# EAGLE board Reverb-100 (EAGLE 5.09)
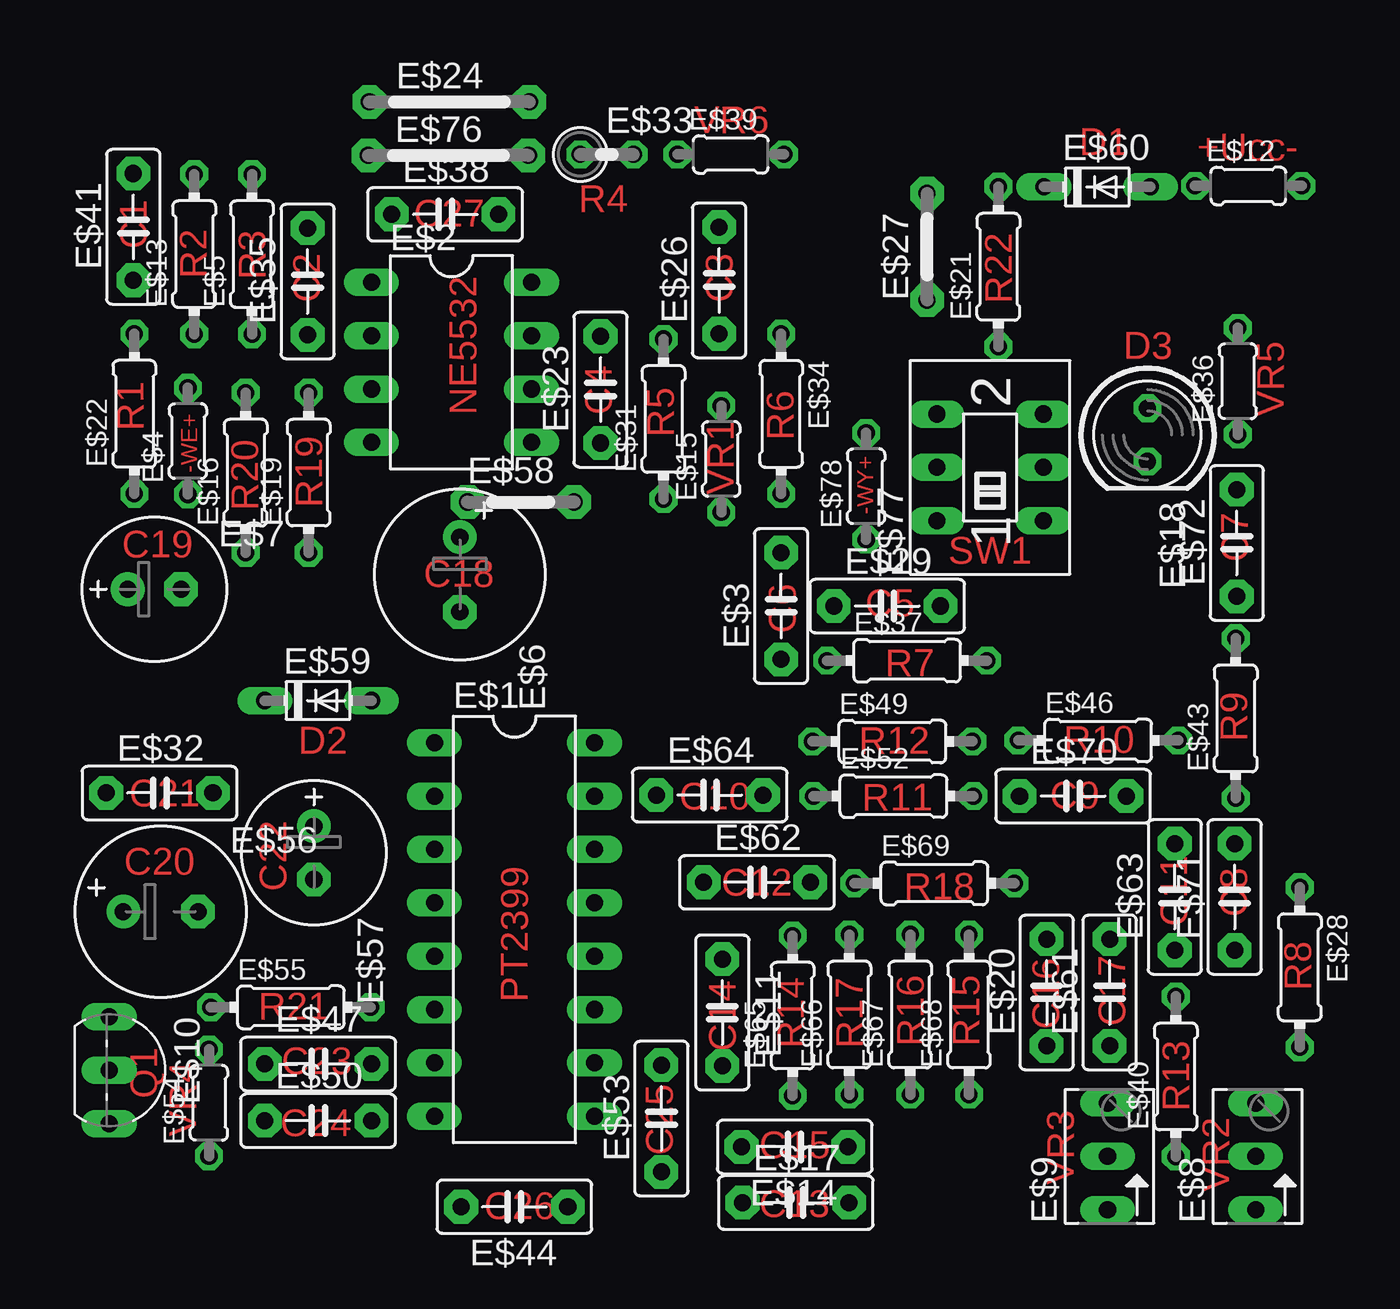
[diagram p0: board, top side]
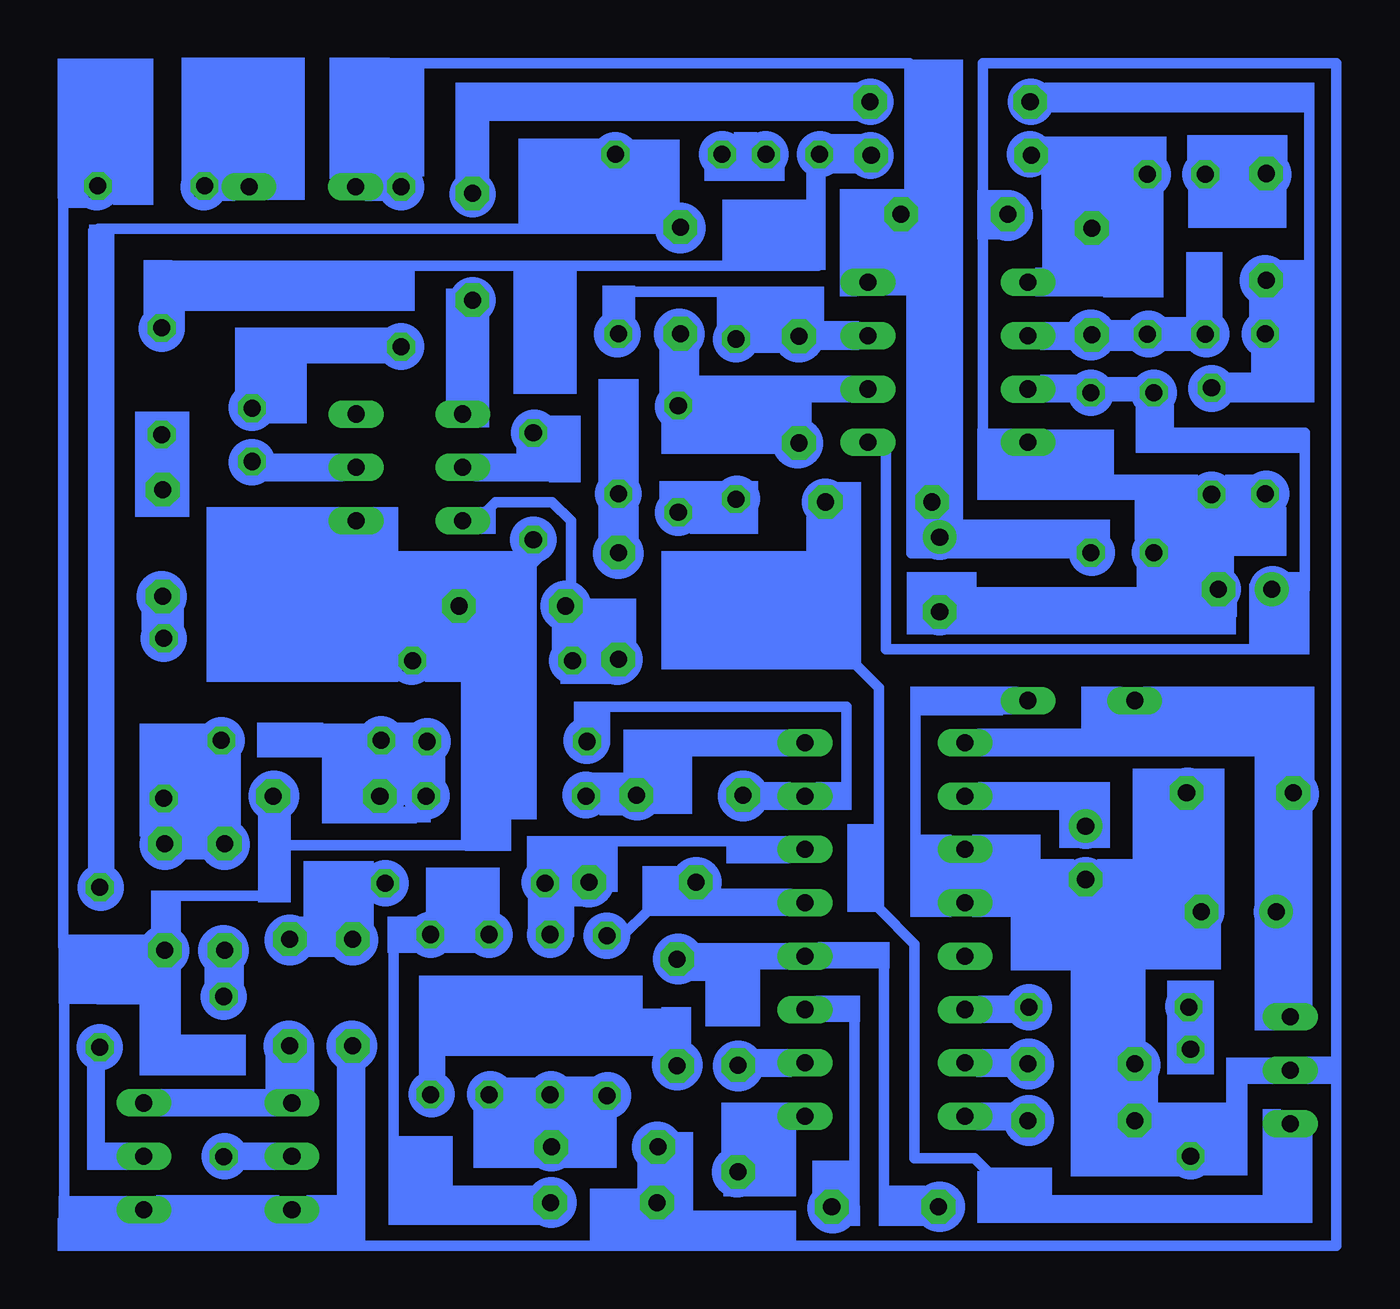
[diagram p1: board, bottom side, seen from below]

No outline drawn. Coordinates in mm, seen from the top.
Copper layers (1*16): Top 0.035mm / dielectric 1.5mm / Bottom 0.035mm
Design rules "default": minimum track width 10mil, minimum drill 24mil, track to track 8mil, track to pad 8mil, pad to pad 8mil, via to via 8mil, smd to smd 8mil, copper to edge 40mil, drill to drill 8mil, minimum pad ring 10mil, minimum via ring 8mil, stop-mask expansion 4mil, vias tented up to drill 0mil, thermal gap 10mil

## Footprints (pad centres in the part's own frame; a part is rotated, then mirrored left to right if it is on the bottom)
DIL16 = drill 0.813 long: 1 -8.89,-3.81; 2 -6.35,-3.81; 3 -3.81,-3.81; 4 -1.27,-3.81; 5 1.27,-3.81; 6 3.81,-3.81; 7 6.35,-3.81; 8 8.89,-3.81; 9 8.89,3.81; 10 6.35,3.81; 11 3.81,3.81; 12 1.27,3.81; 13 -1.27,3.81; 14 -3.81,3.81; 15 -6.35,3.81; 16 -8.89,3.81
DIL08 = drill 0.813 long: 1 -3.81,-3.81; 2 -1.27,-3.81; 3 1.27,-3.81; 4 3.81,-3.81; 5 3.81,3.81; 6 1.27,3.81; 7 -1.27,3.81; 8 -3.81,3.81
C5B2.5 = drill 0.813 pad 1.6 octagon: 1 -2.54,0; 2 2.54,0
0204/5 = drill 0.813 octagon: 1 -2.54,0; 2 2.54,0
0204/7 = drill 0.813 octagon: 1 -3.81,0; 2 3.81,0
E3,5-8 = drill 0.813 pad 1.6 round: + -1.778,0 | drill 0.813 pad 1.6 octagon: - 1.778,0
E2,5-7 = drill 0.813 pad 1.6 round: + -1.27,0 | drill 0.813 pad 1.6 octagon: - 1.27,0
B64Y = drill 0.813 long: A 2.54,0; E -2.54,0; S 0,0
TO92-CBE = drill 0.813 long: B 0,0; C -2.54,0; E 2.54,0
LED5MM = drill 0.813 octagon: A -1.27,0; K 1.27,0
07 = drill 0.813 pad 1.6 octagon: 1 -3.81,0; 2 3.81,0
05 = drill 0.813 pad 1.6 octagon: 1 -2.54,0; 2 2.54,0
0207/2V = drill 0.813 octagon: 1 -1.27,0; 2 1.27,0
DO34-5 = drill 0.813 long: A 2.54,0; C -2.54,0
A68-A31 = drill 0.813 long: 1 -2.54,-2.54; 2 0,-2.54; 3 2.54,-2.54; 4 -2.54,2.54; 5 0,2.54; 6 2.54,2.54

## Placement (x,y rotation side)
E$1  [DIL16]  21.7,15.3 270 top
E$2  [DIL08]  18.7,42.3 270 top
E$3  [C5B2.5]  34.4,30.7 90 top
E$4  [0204/5]  6.15,38.55 90 top
E$5  [0204/7]  9.2,47.45 90 top
E$6  [E3,5-8]  19.1,32.2 270 top
E$7  [E2,5-7]  4.55,31.5 0 top
E$8  [B64Y]  57,4.5 90 top
E$9  [B64Y]  49.95,4.5 90 top
E$10  [TO92-CBE]  2.4,8.6 270 top
E$11  [C5B2.5]  31.6,11.35 270 top
E$12  [0204/5]  56.65,50.7 0 top
E$13  [0204/7]  6.45,47.45 90 top
E$14  [C5B2.5]  35.05,4.95 180 top
E$15  [0204/5]  31.55,37.7 90 top
E$16  [0204/7]  8.9,37.05 90 top
E$17  [C5B2.5]  35.1,2.3 0 top
E$18  [LED5MM]  51.85,38.85 270 top
E$19  [0204/7]  11.9,37.05 90 top
E$20  [C5B2.5]  47.05,12.3 90 top
E$21  [0204/7]  44.75,46.85 90 top
E$22  [0204/7]  3.6,39.85 90 top
E$23  [C5B2.5]  25.8,41 90 top
E$24  [07]  18.6,54.7 0 top
E$26  [C5B2.5]  31.45,46.2 90 top
E$27  [05]  41.35,47.8 90 top
E$28  [0204/7]  59.1,13.5 270 top
E$29  [C5B2.5]  39.45,30.7 0 top
E$31  [0204/7]  28.8,39.6 90 top
E$32  [C5B2.5]  4.8,21.8 0 top
E$33  [0207/2V]  26.1,52.2 0 top
E$34  [0204/7]  34.4,39.85 270 top
E$35  [C5B2.5]  11.85,46.15 90 top
E$36  [0204/5]  56.15,41.4 90 top
E$37  [0204/7]  40.4,28.1 0 top
E$38  [C5B2.5]  18.4,49.35 0 top
E$39  [0204/5]  32,52.2 0 top
E$40  [0204/7]  53.2,8.3 90 top
E$41  [C5B2.5]  3.55,48.75 90 top
E$43  [0204/7]  56.05,25.35 90 top
E$44  [C5B2.5]  21.7,2.1 180 top
E$46  [0204/7]  49.5,24.3 0 top
E$47  [C5B2.5]  12.35,8.9 0 top
E$49  [0204/7]  39.7,24.25 0 top
E$50  [C5B2.5]  12.35,6.2 0 top
E$52  [0204/7]  39.75,21.65 0 top
E$53  [C5B2.5]  28.7,6.3 90 top
E$54  [0204/5]  7.15,7.05 90 top
E$55  [0204/7]  11.05,11.6 0 top
E$56  [E3,5-8]  4.85,16.15 0 top
E$57  [E2,5-7]  12.15,18.95 270 top
E$58  [05]  22,35.65 0 top
E$59  [DO34-5]  12.35,26.2 0 top
E$60  [DO34-5]  49.45,50.65 0 top
E$61  [C5B2.5]  50.05,12.3 90 top
E$62  [C5B2.5]  33.25,17.55 0 top
E$63  [C5B2.5]  53.15,16.85 90 top
E$64  [C5B2.5]  31,21.7 0 top
E$65  [0204/7]  34.95,11.2 90 top
E$66  [0204/7]  37.65,11.25 90 top
E$67  [0204/7]  40.55,11.25 90 top
E$68  [0204/7]  43.35,11.25 90 top
E$69  [0204/7]  41.7,17.5 0 top
E$70  [C5B2.5]  48.3,21.65 0 top
E$71  [C5B2.5]  56,16.85 90 top
E$72  [C5B2.5]  56.1,33.7 90 top
E$76  [07]  18.55,52.15 0 top
E$77  [A68-A31]  44.35,37.3 90 top
E$78  [0204/5]  38.45,36.4 90 top

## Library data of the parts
E$1 E$2 = analog-devices
E$3 E$11 E$14 E$17 E$20 E$23 E$26 E$29 E$32 E$35 E$38 E$41 E$44 E$47 E$50 E$53 E$61-E$64 E$70-E$72 = capacitor-wima
E$4-E$7 E$12 E$13 E$15 E$16 E$19 E$21 E$22 E$28 E$31 E$33 E$34 E$36 E$37 E$39 E$40 E$43 E$46 E$49 E$52 E$54-E$57 E$65-E$69 E$78 = rcl
E$8 E$9 = pot
E$10 = transistor
E$18 = led
E$24 E$27 E$58 E$76 = jumper
E$59 E$60 = diode
E$77 = switch

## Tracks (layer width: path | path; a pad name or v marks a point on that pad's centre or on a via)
S$1
  Bottom 0.5: 24.5,14 21.75,14 21.75,3
S$2
  Bottom 0.5: 26.4,6.4 28.75,6.4 28.75,4.65
S$3
  Bottom 0.5: 16.65,16.5 9.8,16.5 9.8,9.85
S$4
  Bottom 0.5: 16.9,21.65 12.15,21.65 12.15,20.95
S$5
  Bottom 0.5: 16.95,24.3 2.25,24.3 2.25,22.7
S$6
  Bottom 0.5: 2.2,20.7 2.2,15.65
S$7
  Bottom 0.5: 3.3,8.55 5.05,8.55 5.05,4.4 6.1,4.4
S$8
  Bottom 0.5: 17.8,26.15 20.25,26.15 20.25,19 19.05,19
S$9
  Bottom 0.5: 16.9,49.35 17.05,49.35 17.05,38.4
S$10
  Bottom 0.5: 20.85,48.55 20.85,46.1 21.65,46.1
S$11
  Bottom 0.5: 11.85,47.7 11.85,46.2 13.8,46.2
S$12
  Bottom 0.5: 10.15,51.3 11.8,51.3 11.8,49.55
S$13
  Bottom 0.5: 5.1,41 3.6,41 3.6,42.85
S$14
  Bottom 0.5: 7.15,36 14.05,36 14.05,38.55
S$15
  Bottom 0.5: 12.85,33.2 20.45,33.2 20.45,48.45
S$16
  Bottom 0.5: 2.15,31.5 1.7,31.5 1.7,38.95 8.9,38.95 8.9,40
S$17
  Bottom 0.5: 18.15,30.45 8.85,30.45 8.85,32.4
S$18
  Bottom 0.5: 21.65,38.45 21.65,28.65 3,28.65
S$19
  Bottom 0.5: 13.8,52.2 13.8,49.15 12.6,49.15
S$20
  Bottom 0.5: 29,41.1 31.5,41.1 31.5,42.7
S$21
  Bottom 0.5: 9,2.1 3.25,2.1 3.25,6.25
S$22
  Bottom 0.5: 17.05,49.7 17.05,56.5
S$23
  Bottom 0.5: 20.55,50.4 20.55,53.05
S$24
  Bottom 0.5: 28.9,44.25 28.9,45.65 34.45,45.65 34.45,44.55
S$25
  Bottom 0.5: 26.35,19.5 34.85,19.5 35.6,18.85
S$26
  Bottom 0.5: 26.2,16.2 33,16.2 34.15,15.05
S$27
  Bottom 0.5: 47.15,8.9 47.15,0.25 32.25,0.25
S$28
  Bottom 0.5: 32.35,0.25 0.2,0.25 0.2,56.55 17.05,56.55
S$29
  Bottom 0.5: 24.65,11.4 23.15,11.4 23.15,1.95
S$30
  Bottom 0.5: 31.65,10 31.65,11.3 43.45,11.3 43.45,8.3 43.4,8.3
S$31
  Bottom 0.5: 38.7,2.25 45.1,2.25 45.1,15.15 44.1,15.15
S$32
  Bottom 0.5: 26.6,24.25 33.4,24.25 33.4,22.65
S$33
  Bottom 0.5: 35.95,25.35 35.4,25.9 23.55,25.9 23.55,21.65 24.65,21.65
S$34
  Bottom 0.5: 50.75,20.65 50.75,16.9 56,16.9 56,15.3
S$35
  Bottom 0.5: 58,4.5 59.1,4.5 59.1,8.9
S$36
  Bottom 0.5: 57.2,14.25 59.1,14.25 59.1,12 60.8,12 60.8,1.95 57.85,1.95 57.85,2
S$37
  Bottom 0.5: 32.55,48.65 59.15,48.65 59.1,18.05
S$38
  Bottom 0.5: 23.05,27.85 22,26.8 22,16.3 20.3,14.6 20.3,4.4 17.45,4.4 15.65,2.6
S$39
  Bottom 0.5: 24.9,51.15 24.9,46.9 56.25,46.9
S$40
  Bottom 0.5: 20.55,53.1 20.55,56.55 45.6,56.55 45.6,50.4
S$41
  Bottom 0.5: 60.4,50.75 60.85,50.75 60.85,14.5
S$42
  Bottom 0.5: 23.1,27.95 23.1,35.7 23.75,35.7
S$43
  Bottom 0.5: 50.3,19.3 41.65,19.3 41.65,29.8
S$44
  Bottom 0.5: 40.95,30.75 40.45,30.75 38.05,33.15
S$45
  Bottom 0.5: 36.65,31.8 36.65,34.75 37.55,35.65 40.25,35.65 41,34.9
S$46
  Bottom 0.5: 45.7,43 51.85,43 51.85,41.05
S$47
  Bottom 0.5: 3.55,40.75 1.5,40.75 1.5,54.75 13.95,54.75
S$48
  Bottom 0.5: 23.35,54.8 41.35,54.8 41.35,51.15
S$49
  Bottom 0.5: 56.3,37.15 56.25,37.15
(copper drawn outside any net)
  shapes: Bottom area x328, Bottom circle x122

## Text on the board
Top: VR6 | D1 | +Ucc- | C27 | R4 | C1 | R2 | R3 | C2 | C3 | R22 | VR5 | D3 | NE5532 | C4 | R1 | R5 | R6 | -WY+ | -WE+ | VR1 | R20 | R19 | C19 | C18 | SW1 | C7 | C5 | C6 | R7 | D2 | R12 | R10 | R9 | C21 | C10 | R11 | C9 | C22 | C20 | C12 | R18 | C8 | C11 | PT2399 | R8 | R21 | C16 | C17 | Q1 | C14 | R14 | R17 | R16 | R15 | C23 | R13 | VR4 | C24 | C25 | C15 | VR3 | VR2 | C26 | C13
